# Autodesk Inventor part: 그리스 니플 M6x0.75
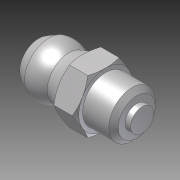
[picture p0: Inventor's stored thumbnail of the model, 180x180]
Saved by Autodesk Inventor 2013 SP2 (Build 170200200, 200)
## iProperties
Created: 2025-04
Part Number: 그리스 니플 M6x0.75
Material: Generic
Document SubType Name: Modeling
Designer: 601
Density: 1 g/cm^3
Author: 601
변환 표준: STEP AP214IS
전처리기: Build: 200, Release: 2013 SP2 Update 6 - Date: Thu 07/17/2014
전송 단위: 밀리미터
불확실성: 0.01
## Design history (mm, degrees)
node "그리스 니플 M6x0.751"
body "Solid1"
node "기준1"
